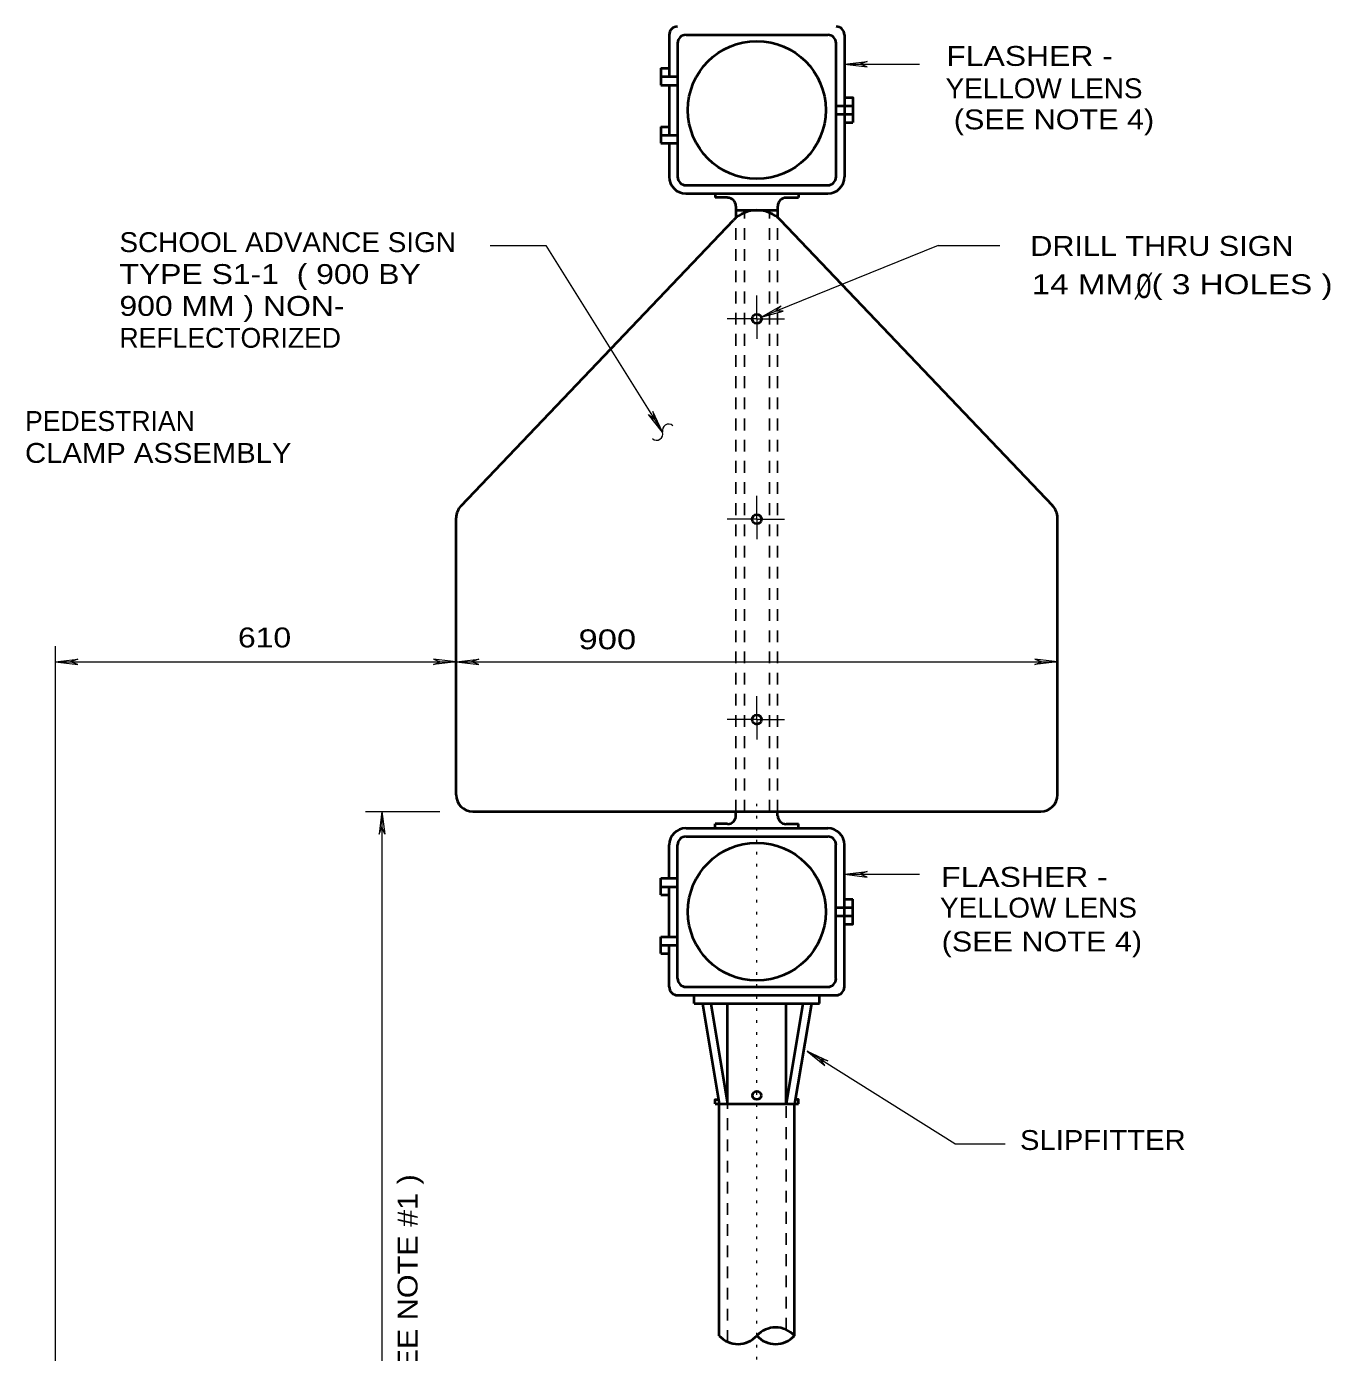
# Model space of a CAD drawing. Extents: x 312583 to 312854, y 144419 to 144597.
# Drawn here: x 312744.9 to 312794.8, y 144475.3 to 144526 of the extents above; entities that cross this region are included whole.
import ezdxf
from ezdxf.enums import TextEntityAlignment as Align

# ---------------------------------------------------------------- set-up
doc = ezdxf.new("R2010")
doc.units = 0
doc.header["$LTSCALE"] = 0.3
doc.linetypes.add('DOTTED', pattern=[1.5, 0.3, -1.2])
doc.linetypes.add('SHORT_DASHED', pattern=[2.7, 1.5, -1.2])
doc.layers.add('1', color=7, linetype='Continuous', lineweight=40)
doc.layers.add('2', color=7, linetype='Continuous', lineweight=13)

msp = doc.modelspace()

# ---------------------------------------------------------------- linework, layer by layer
at = {"layer": '1'}
for p, q in [((312769.5016, 144525.7016), (312769.5016, 144524.1069)), ((312769.8236, 144525.3873), (312769.8236, 144520.2736)), ((312770.1456, 144525.7016), (312775.566, 144525.7016)), ((312775.8803, 144525.3873), (312775.8803, 144520.2736)), ((312776.2023, 144525.7016), (312776.2023, 144520.2736)), ((312769.1873, 144524.4289), (312769.5016, 144524.4289)), ((312769.1873, 144524.4289), (312769.1873, 144523.7849)), ((312769.1873, 144524.1069), (312769.8236, 144524.1069)), ((312769.1873, 144523.7849), (312769.8236, 144523.7849)), ((312769.5016, 144523.7849), (312769.5016, 144521.8683)), ((312775.8803, 144522.9876), (312776.2023, 144522.9876)), ((312776.2023, 144522.9876), (312776.5243, 144522.9876)), ((312775.8803, 144522.6656), (312776.2023, 144522.6656)), ((312776.2023, 144522.6656), (312776.5243, 144522.6656)), ((312776.2023, 144522.3513), (312776.5243, 144522.3513)), ((312769.1873, 144522.1903), (312769.5016, 144522.1903)), ((312769.1873, 144522.1903), (312769.1873, 144521.5539)), ((312769.1873, 144521.8683), (312769.8236, 144521.8683)), ((312769.1873, 144521.5539), (312769.8236, 144521.5539)), ((312769.5016, 144521.5539), (312769.5016, 144520.2736)), ((312770.1456, 144519.9516), (312775.566, 144519.9516)), ((312770.1456, 144519.6373), (312775.566, 144519.6373)), ((312771.2573, 144519.6373), (312771.2573, 144519.4763)), ((312771.7326, 144519.4763), (312771.2573, 144519.4763)), ((312773.9713, 144519.4763), (312774.4466, 144519.4763)), ((312774.4466, 144519.6373), (312774.4466, 144519.4763)), ((312772.0546, 144519.1543), (312772.0546, 144518.7096)), ((312772.0546, 144518.9933), (312773.6493, 144518.9933)), ((312772.3766, 144518.9013), (312772.3766, 144518.9933)), ((312773.335, 144518.9013), (312773.335, 144518.9933)), ((312773.6493, 144519.1543), (312773.6493, 144518.7173)), ((312761.5436, 144507.6849), (312771.955, 144518.6176)), ((312784.168, 144507.6849), (312773.7643, 144518.6176)), ((312761.352, 144496.6373), (312761.352, 144507.2326)), ((312784.352, 144496.6373), (312784.352, 144507.2326)), ((312761.9883, 144495.9933), (312783.7156, 144495.9933)), ((312772.0546, 144495.8323), (312772.0546, 144495.9933)), ((312773.6493, 144495.8323), (312773.6493, 144495.9933)), ((312771.7326, 144495.5179), (312771.2573, 144495.5179)), ((312771.2573, 144495.3569), (312771.2573, 144495.5179)), ((312773.9713, 144495.5179), (312774.4466, 144495.5179)), ((312774.4466, 144495.3569), (312774.4466, 144495.5179)), ((312770.1456, 144495.3569), (312775.566, 144495.3569)), ((312770.1456, 144495.0349), (312775.566, 144495.0349)), ((312769.5016, 144493.4403), (312769.5016, 144494.7206)), ((312769.8236, 144489.6069), (312769.8236, 144494.7206)), ((312775.8803, 144489.6069), (312775.8803, 144494.7206)), ((312776.2023, 144489.2849), (312776.2023, 144494.7206)), ((312769.1873, 144492.8039), (312769.1873, 144493.4403)), ((312769.1873, 144493.4403), (312769.8236, 144493.4403)), ((312769.1873, 144493.1183), (312769.8236, 144493.1183)), ((312769.5016, 144491.2016), (312769.5016, 144493.1183)), ((312769.1873, 144492.8039), (312769.5016, 144492.8039)), ((312776.2023, 144492.6429), (312776.5243, 144492.6429)), ((312775.8803, 144492.3209), (312776.2023, 144492.3209)), ((312775.8803, 144491.9989), (312776.2023, 144491.9989)), ((312776.2023, 144492.3209), (312776.5243, 144492.3209)), ((312776.2023, 144491.9989), (312776.5243, 144491.9989)), ((312769.1873, 144490.5653), (312769.1873, 144491.2016)), ((312769.1873, 144491.2016), (312769.8236, 144491.2016)), ((312769.1873, 144490.8873), (312769.8236, 144490.8873)), ((312769.5016, 144489.2849), (312769.5016, 144490.8873)), ((312769.1873, 144490.5653), (312769.5016, 144490.5653)), ((312769.8236, 144488.9706), (312775.8803, 144488.9706)), ((312770.1456, 144489.2849), (312775.566, 144489.2849)), ((312770.46, 144488.6486), (312770.46, 144488.9706)), ((312775.244, 144488.6486), (312775.244, 144488.9706)), ((312770.46, 144488.6486), (312775.244, 144488.6486)), ((312770.7743, 144488.6486), (312771.4106, 144484.8153)), ((312771.0963, 144488.6486), (312771.7326, 144484.8153)), ((312771.7326, 144484.8153), (312771.7326, 144488.6486)), ((312773.9713, 144484.8153), (312773.9713, 144488.6486)), ((312773.9713, 144484.8153), (312773.9713, 144488.6486)), ((312774.6076, 144488.6486), (312773.9713, 144484.8153)), ((312774.9373, 144488.6486), (312774.2933, 144484.8153)), ((312771.2573, 144484.8153), (312774.4466, 144484.8153)), ((312771.4183, 144475.9373), (312771.4183, 144484.8153)), ((312774.2933, 144475.9373), (312774.2933, 144484.8153))]:
    msp.add_line(p, q, dxfattribs=at)
at = {"layer": '1', "linetype": 'SHORT_DASHED', "lineweight": 25}
for p, q in [((312772.3766, 144495.9933), (312772.3766, 144518.9013)), ((312773.335, 144495.9933), (312773.335, 144518.9013)), ((312772.0546, 144495.9933), (312772.0546, 144518.7096)), ((312773.6493, 144495.9933), (312773.6493, 144518.7173)), ((312771.7326, 144475.7073), (312771.7326, 144484.8153)), ((312773.9713, 144476.1749), (312773.9713, 144484.8153))]:
    msp.add_line(p, q, dxfattribs=at)
at = {"layer": '1', "linetype": 'DOTTED', "lineweight": 13}
msp.add_line((312772.852, 144457.0926), (312772.852, 144496.5069), dxfattribs=at)
at = {"layer": '1'}
for points in [[(312776.2023, 144523.3096), (312776.5243, 144523.3096), (312776.5243, 144522.3513)], [(312776.2023, 144491.6846), (312776.5243, 144491.6846), (312776.5243, 144492.6429)], [(312771.2573, 144484.8153), (312771.2573, 144484.9763), (312771.3876, 144484.9763)], [(312774.4466, 144484.8153), (312774.4466, 144484.9763), (312774.324, 144484.9763)]]:
    msp.add_lwpolyline(points, dxfattribs=at)
for centre, radius in [((312772.8526, 144522.8282), 2.6354), ((312772.8526, 144514.8418), 0.1797), ((312772.8526, 144507.1751), 0.1797), ((312772.8526, 144499.5084), 0.1797), ((312772.8526, 144492.1609), 2.6354), ((312772.8526, 144485.1334), 0.1597)]:
    msp.add_circle(centre, radius, dxfattribs=at)
for centre, radius, start, end in [((312769.8224, 144525.7029), 0.3194, 90, 180), ((312775.8829, 144525.7029), 0.3194, 0, 90), ((312770.1418, 144525.3834), 0.3194, 90, 180), ((312775.5634, 144525.3834), 0.3194, 0, 90), ((312770.1418, 144520.2723), 0.6389, 180, 270), ((312770.1418, 144520.2723), 0.3194, 180, 270), ((312775.5634, 144520.2723), 0.6389, 270, 0), ((312775.5634, 144520.2723), 0.3194, 270, 0), ((312771.7345, 144519.1543), 0.3194, 0, 90), ((312773.9707, 144519.1543), 0.3194, 90, 180), ((312772.859, 144517.7165), 1.2778, 45, 135), ((312761.9915, 144507.2299), 0.6389, 135, 180), ((312783.7137, 144507.2299), 0.6389, 0, 45), ((312761.9915, 144496.6334), 0.6389, 180, 270), ((312783.7137, 144496.6334), 0.6389, 270, 0), ((312771.7345, 144495.8348), 0.3194, 270, 0), ((312773.9707, 144495.8348), 0.3194, 180, 270), ((312770.1418, 144494.7168), 0.6389, 90, 180), ((312770.1418, 144494.7168), 0.3194, 90, 180), ((312775.5634, 144494.7168), 0.6389, 0, 90), ((312775.5634, 144494.7168), 0.3194, 0, 90), ((312770.1418, 144489.6057), 0.3194, 180, 270), ((312775.5634, 144489.6057), 0.3194, 270, 0), ((312769.8224, 144489.2862), 0.3194, 180, 270), ((312775.8829, 144489.2862), 0.3194, 270, 0), ((312773.5714, 144475.2903), 0.9683, 42.07502, 137.92498), ((312772.1339, 144476.5881), 0.9683, 222.07502, 317.92498), ((312773.5714, 144476.5881), 0.9683, 222.07502, 317.92498)]:
    msp.add_arc(centre, radius, start, end, dxfattribs=at)
at = {"layer": '2'}
for p, q in [((312776.2023, 144524.5823), (312777.0686, 144524.6896)), ((312776.2023, 144524.5823), (312779.0696, 144524.5823)), ((312776.2023, 144524.5823), (312777.0686, 144524.4749)), ((312777.0686, 144524.6896), (312776.7926, 144524.5823)), ((312777.0686, 144524.4749), (312776.7926, 144524.5823)), ((312779.7903, 144517.6516), (312773.0206, 144514.9069)), ((312779.7903, 144517.6516), (312782.144, 144517.6516)), ((312787.319, 144515.5816), (312787.9553, 144516.6089)), ((312772.852, 144514.8456), (312772.852, 144515.7349)), ((312773.0206, 144514.9069), (312773.7796, 144515.3363)), ((312773.0206, 144514.9069), (312773.7796, 144515.3363)), ((312773.7796, 144515.3363), (312773.565, 144515.1293)), ((312773.7796, 144515.3363), (312773.565, 144515.1293)), ((312772.852, 144514.8456), (312771.7173, 144514.8456)), ((312772.852, 144514.8456), (312772.852, 144514.0789)), ((312772.852, 144514.8456), (312773.91, 144514.8456)), ((312773.0206, 144514.9069), (312773.864, 144515.1369)), ((312773.0206, 144514.9069), (312773.864, 144515.1369)), ((312773.864, 144515.1369), (312773.565, 144515.1293)), ((312773.864, 144515.1369), (312773.565, 144515.1293)), ((312768.7043, 144511.1809), (312768.942, 144511.0046)), ((312769.2486, 144510.5063), (312768.7043, 144511.1809)), ((312768.8806, 144511.2959), (312768.942, 144511.0046)), ((312769.2486, 144510.5063), (312768.8806, 144511.2959)), ((312772.852, 144507.1789), (312772.852, 144508.0683)), ((312772.852, 144507.1789), (312771.7173, 144507.1789)), ((312772.852, 144507.1789), (312772.852, 144506.4123)), ((312772.852, 144507.1789), (312773.91, 144507.1789)), ((312746.0186, 144502.3183), (312746.0186, 144455.8276)), ((312746.0186, 144501.7203), (312746.885, 144501.8276)), ((312746.0186, 144501.7203), (312761.352, 144501.7203)), ((312746.0186, 144501.7203), (312746.885, 144501.6129)), ((312746.885, 144501.8276), (312746.609, 144501.7203)), ((312746.885, 144501.6129), (312746.609, 144501.7203)), ((312760.4856, 144501.8276), (312760.7616, 144501.7203)), ((312761.352, 144501.7203), (312760.4856, 144501.8276)), ((312760.4856, 144501.6129), (312760.7616, 144501.7203)), ((312761.352, 144501.7203), (312760.4856, 144501.6129)), ((312761.352, 144501.7203), (312762.2183, 144501.8276)), ((312761.352, 144501.7203), (312784.352, 144501.7203)), ((312761.352, 144501.7203), (312762.2183, 144501.6129)), ((312762.2183, 144501.8276), (312761.9423, 144501.7203)), ((312762.2183, 144501.6129), (312761.9423, 144501.7203)), ((312783.4856, 144501.8276), (312783.7616, 144501.7203)), ((312784.352, 144501.7203), (312783.4856, 144501.8276)), ((312783.4856, 144501.6129), (312783.7616, 144501.7203)), ((312784.352, 144501.7203), (312783.4856, 144501.6129)), ((312772.852, 144499.5123), (312772.852, 144500.4016)), ((312772.852, 144499.5123), (312771.7173, 144499.5123)), ((312772.852, 144499.5123), (312772.852, 144498.7456)), ((312772.852, 144499.5123), (312773.91, 144499.5123)), ((312757.8866, 144495.9933), (312760.731, 144495.9933)), ((312758.5153, 144495.9933), (312758.408, 144495.1269)), ((312758.5153, 144495.9933), (312758.5153, 144455.8123)), ((312758.5153, 144495.9933), (312758.6226, 144495.1269)), ((312758.408, 144495.1269), (312758.5153, 144495.4029)), ((312758.6226, 144495.1269), (312758.5153, 144495.4029)), ((312776.2023, 144493.5936), (312777.0686, 144493.7009)), ((312776.2023, 144493.5936), (312779.0696, 144493.5936)), ((312776.2023, 144493.5936), (312777.0686, 144493.4863)), ((312777.0686, 144493.7009), (312776.7926, 144493.5936)), ((312777.0686, 144493.4863), (312776.7926, 144493.5936)), ((312780.419, 144483.2819), (312774.7763, 144486.8316)), ((312774.7763, 144486.8316), (312775.451, 144486.2796)), ((312774.7763, 144486.8316), (312775.566, 144486.4559)), ((312775.451, 144486.2796), (312775.2746, 144486.5173)), ((312775.566, 144486.4559), (312775.2746, 144486.5173)), ((312780.419, 144483.2819), (312782.351, 144483.2819))]:
    msp.add_line(p, q, dxfattribs=at)
msp.add_lwpolyline([(312762.6553, 144517.6516), (312764.7866, 144517.6516), (312769.2486, 144510.5063)], dxfattribs=at)
for centre, start, end in [((312769.4796, 144510.5756), 46.98741, 196.98741), ((312769.0215, 144510.4357), 226.98741, 16.98741)]:
    msp.add_arc(centre, 0.2395, start, end, dxfattribs=at)

# ---------------------------------------------------------------- texts
for s, width, p in [('FLASHER - ', 1.2, (312780.0982, 144524.516)), ('YELLOW LENS', 1.05, (312780.0699, 144523.2799)), ('(SEE NOTE 4)', 1.15, (312780.3848, 144522.0896)), ('SCHOOL ADVANCE SIGN', 1.05, (312748.4781, 144517.3937)), ('DRILL THRU SIGN', 1.15, (312783.3117, 144517.2482)), ('TYPE S1-1  ( 900 BY ', 1.2, (312748.4781, 144516.1737)), ('14 MM  ( 3 HOLES )', 1.25, (312783.3621, 144515.7839)), ('900 MM ) NON-', 1.2, (312748.4781, 144514.9537)), ('CLAMP ASSEMBLY', 1.1, (312744.868, 144509.3313)), ('610 ', 1.2, (312753.0098, 144502.2713)), ('900 ', 1.3, (312766.0341, 144502.2005)), ('FLASHER - ', 1.2, (312779.9008, 144493.1115)), ('YELLOW LENS', 1.05, (312779.8572, 144491.9367)), ('(SEE NOTE 4)', 1.15, (312779.9214, 144490.641)), ('SLIPFITTER', 1.1, (312782.9166, 144483.0471))]:
    msp.add_text(s, height=0.76, dxfattribs=dict(at, width=width)).set_placement(p)
at = {"layer": '2', "width": 0.85}
msp.add_text('0', height=0.92, dxfattribs=at).set_placement((312787.6563, 144515.6353), align=Align.CENTER)
at = {"layer": '2'}
for s, p in [('REFLECTORIZED', (312748.4781, 144513.7337)), ('PEDESTRIAN', (312744.868, 144510.5513))]:
    msp.add_text(s, height=0.76, dxfattribs=at).set_placement(p)
at = {"layer": '2', "width": 1.15}
msp.add_text('( SEE NOTE #1 )', height=0.76, rotation=90, dxfattribs=at).set_placement((312759.877, 144473.1561))

doc.saveas('drawing.dxf')
